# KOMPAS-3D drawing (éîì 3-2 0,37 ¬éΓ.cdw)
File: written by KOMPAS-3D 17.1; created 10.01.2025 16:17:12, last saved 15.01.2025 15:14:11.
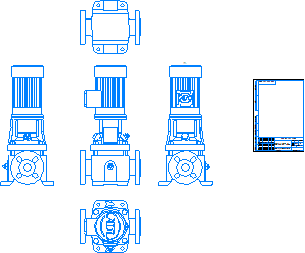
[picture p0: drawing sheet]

Sheet 1: A4, portrait

Title block, sheet 1: name: ВМН 3-2 0,37 кВт; designation: ВМН 3-2 0,37 кВт; material: Сталь 10  ГОСТ 1050-2013; mass: 63,56; sheets: 1; sheet format: A4; stored path: \\adlc.lan\data\АДЛ_ПКД\3D-модели\ADL production\Насосы ГРАНПАМП\Насосы ВМН\ВМН3\KOMPAS 3D\3-2 0,37 кВт _ ВМН.cdw

Views: Проекционный вид 2, Проекционный вид 3, Проекционный вид 4, Проекционный вид 5
Referenced files in \\adlc.lan\data\АДЛ_ПКД\3D-модели\ADL production\Насосы ГРАНПАМП\Насосы ВМН\ВМН3\KOMPAS 3D\: ВМН 3-2 0,37 кВт.m3d
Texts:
  Andrey
  АДЛ
Dimensions and other numbers on the sheet: 1:1; 1; 63,56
